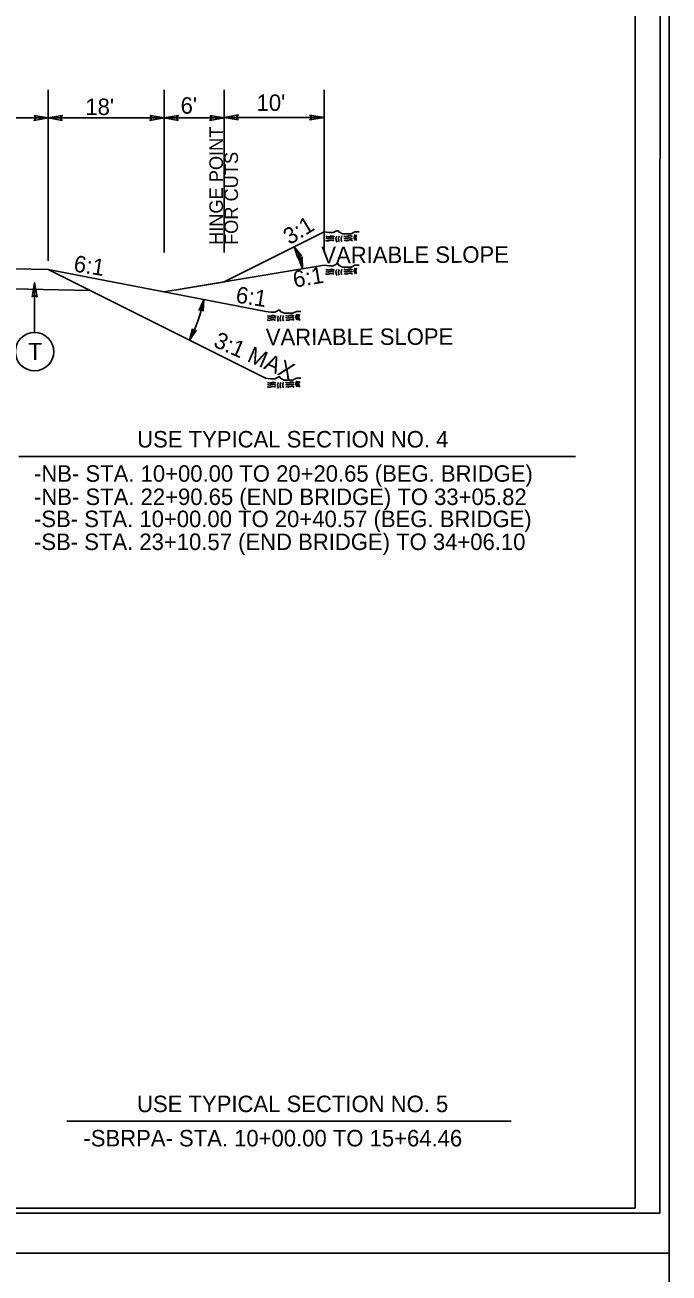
# Model space of a CAD drawing. Extents: x 2241081 to 2251104, y 658534 to 663427.
# Drawn here: x 2246759 to 2247081, y 660714 to 661339 of the extents above; entities that cross this region are included whole.
import ezdxf

# ---------------------------------------------------------------- set-up
doc = ezdxf.new("R2010")
doc.units = 0
for name, color, linetype in [('Old_Level_1', 7, 'Continuous'), ('Old_Level_2', 7, 'Continuous'), ('Prop Dimension', 7, 'Continuous'), ('Prop Dimension Text', 7, 'Continuous'), ('Prop PHM Text', 7, 'Continuous'), ('Sheet Cutting Line CELL', 7, 'Continuous'), ('Sheet Plan CELL', 7, 'Continuous'), ('Sheet Plot Border Inside CELL', 7, 'Continuous'), ('Sheet Plot Border Outside CELL', 7, 'Continuous'), ('Typical Hinge Slope Interstate CELL', 7, 'Continuous'), ('Typical ID Circle CELL', 7, 'Continuous'), ('Typical Terminator CELL', 7, 'Continuous'), ('Typical Text ID Circle CELL', 7, 'Continuous'), ('Typical Text Label CELL', 7, 'Continuous')]:
    doc.layers.add(name, color=color, linetype=linetype)

msp = doc.modelspace()

# ---------------------------------------------------------------- linework, layer by layer
at = {"layer": 'Old_Level_1'}
for p, q in [((2246908.21, 661235.45), (2246858.21, 661210.45)), ((2246858.21, 661210.45), (2246908.21, 661218.78)), ((2246770.2, 661216.62), (2246879.03, 661195.67)), ((2246858.21, 661210.45), (2246836.21, 661206.78))]:
    msp.add_line(p, q, dxfattribs=at)
for points in [[(2246908.21, 661235.45), (2246910.68, 661235.14), (2246911.29, 661235.14), (2246912.22, 661235.14), (2246912.83, 661235.14), (2246913.45, 661235.45), (2246914.07, 661235.76), (2246914.68, 661236.07), (2246915.3, 661236.07), (2246915.61, 661235.45), (2246916.22, 661235.14), (2246916.84, 661234.83), (2246917.46, 661234.53), (2246918.07, 661234.53), (2246918.69, 661234.53), (2246919.3, 661234.53), (2246919.92, 661234.53), (2246920.54, 661234.53), (2246921.15, 661234.53), (2246921.77, 661234.53), (2246922.39, 661234.83), (2246923, 661235.14), (2246923.62, 661235.45), (2246924.54, 661235.45), (2246925.16, 661235.45), (2246925.78, 661235.45)], [(2246908.21, 661218.78), (2246910.68, 661218.48), (2246911.29, 661218.48), (2246912.22, 661218.48), (2246912.83, 661218.48), (2246913.45, 661218.78), (2246914.07, 661219.09), (2246914.68, 661219.4), (2246915.3, 661219.4), (2246915.61, 661218.78), (2246916.22, 661218.48), (2246916.84, 661218.17), (2246917.46, 661217.86), (2246918.07, 661217.86), (2246918.69, 661217.86), (2246919.3, 661217.86), (2246919.92, 661217.86), (2246920.54, 661217.86), (2246921.15, 661217.86), (2246921.77, 661217.86), (2246922.39, 661218.17), (2246923, 661218.48), (2246923.62, 661218.78), (2246924.54, 661218.78), (2246925.16, 661218.78), (2246925.78, 661218.78)], [(2246879.03, 661195.67), (2246881.5, 661195.36), (2246882.11, 661195.36), (2246883.04, 661195.36), (2246883.66, 661195.36), (2246884.27, 661195.67), (2246884.89, 661195.98), (2246885.5, 661196.29), (2246886.12, 661196.29), (2246886.43, 661195.67), (2246887.05, 661195.36), (2246887.66, 661195.05), (2246888.28, 661194.75), (2246888.89, 661194.75), (2246889.51, 661194.75), (2246890.13, 661194.75), (2246890.74, 661194.75), (2246891.36, 661194.75), (2246891.97, 661194.75), (2246892.59, 661194.75), (2246893.21, 661195.05), (2246893.82, 661195.36), (2246894.44, 661195.67), (2246895.36, 661195.67), (2246895.98, 661195.67), (2246896.6, 661195.67)], [(2246879.01, 661162.21), (2246881.48, 661161.9), (2246882.09, 661161.9), (2246883.02, 661161.9), (2246883.63, 661161.9), (2246884.25, 661162.21), (2246884.87, 661162.52), (2246885.48, 661162.83), (2246886.1, 661162.83), (2246886.41, 661162.21), (2246887.02, 661161.9), (2246887.64, 661161.59), (2246888.26, 661161.28), (2246888.87, 661161.28), (2246889.49, 661161.28), (2246890.11, 661161.28), (2246890.72, 661161.28), (2246891.34, 661161.28), (2246891.95, 661161.28), (2246892.57, 661161.28), (2246893.19, 661161.59), (2246893.8, 661161.9), (2246894.42, 661162.21), (2246895.34, 661162.21), (2246895.96, 661162.21), (2246896.58, 661162.21)]]:
    msp.add_lwpolyline(points, dxfattribs=at)
for points in [[(2246913.19, 661230.94), (2246911.69, 661231.37), (2246910.1, 661230.96), (2246908.95, 661231.22)], [(2246913.19, 661230.94), (2246911.69, 661231.37), (2246910.1, 661230.96), (2246908.95, 661231.22)], [(2246913.35, 661232.03), (2246911.84, 661232.46), (2246910.25, 661232.05), (2246909.11, 661232.31)], [(2246913.35, 661232.03), (2246911.84, 661232.46), (2246910.25, 661232.05), (2246909.11, 661232.31)], [(2246913.39, 661232.97), (2246911.88, 661233.4), (2246910.29, 661233), (2246909.14, 661233.25)], [(2246913.39, 661232.97), (2246911.88, 661233.4), (2246910.29, 661233), (2246909.14, 661233.25)], [(2246914.63, 661233.26), (2246914.21, 661232.02), (2246914.66, 661230.37)], [(2246914.63, 661233.26), (2246914.21, 661232.02), (2246914.66, 661230.37)], [(2246915.84, 661233.37), (2246915.42, 661232.13), (2246915.87, 661230.48)], [(2246915.84, 661233.37), (2246915.42, 661232.13), (2246915.87, 661230.48)], [(2246917.15, 661233.47), (2246916.74, 661232.23), (2246917.18, 661230.58)], [(2246917.15, 661233.47), (2246916.74, 661232.23), (2246917.18, 661230.58)], [(2246922.41, 661233.12), (2246920.91, 661233.55), (2246919.32, 661233.14), (2246918.18, 661233.4)], [(2246922.41, 661233.12), (2246920.91, 661233.55), (2246919.32, 661233.14), (2246918.18, 661233.4)], [(2246922.42, 661232.07), (2246920.91, 661232.5), (2246919.33, 661232.09), (2246918.19, 661232.35)], [(2246922.42, 661232.07), (2246920.91, 661232.5), (2246919.33, 661232.09), (2246918.19, 661232.35)], [(2246922.54, 661231.01), (2246921.03, 661231.44), (2246919.44, 661231.04), (2246918.29, 661231.3)], [(2246922.54, 661231.01), (2246921.03, 661231.44), (2246919.44, 661231.04), (2246918.29, 661231.3)], [(2246923.74, 661234.09), (2246923.32, 661232.84), (2246923.77, 661231.2)], [(2246923.74, 661234.09), (2246923.32, 661232.84), (2246923.77, 661231.2)], [(2246924.52, 661234), (2246924.1, 661232.76), (2246924.56, 661231.11)], [(2246924.52, 661234), (2246924.1, 661232.76), (2246924.56, 661231.11)], [(2246923.74, 661217.42), (2246923.32, 661216.18), (2246923.77, 661214.53)], [(2246923.74, 661217.42), (2246923.32, 661216.18), (2246923.77, 661214.53)], [(2246924.52, 661217.34), (2246924.1, 661216.09), (2246924.56, 661214.45)], [(2246924.52, 661217.34), (2246924.1, 661216.09), (2246924.56, 661214.45)], [(2246913.19, 661214.27), (2246911.69, 661214.7), (2246910.1, 661214.3), (2246908.95, 661214.56)], [(2246913.19, 661214.27), (2246911.69, 661214.7), (2246910.1, 661214.3), (2246908.95, 661214.56)], [(2246913.35, 661215.37), (2246911.84, 661215.8), (2246910.25, 661215.39), (2246909.11, 661215.65)], [(2246913.35, 661215.37), (2246911.84, 661215.8), (2246910.25, 661215.39), (2246909.11, 661215.65)], [(2246913.39, 661216.31), (2246911.88, 661216.74), (2246910.29, 661216.33), (2246909.14, 661216.59)], [(2246913.39, 661216.31), (2246911.88, 661216.74), (2246910.29, 661216.33), (2246909.14, 661216.59)], [(2246914.63, 661216.6), (2246914.21, 661215.35), (2246914.66, 661213.71)], [(2246914.63, 661216.6), (2246914.21, 661215.35), (2246914.66, 661213.71)], [(2246915.84, 661216.71), (2246915.42, 661215.46), (2246915.87, 661213.81)], [(2246915.84, 661216.71), (2246915.42, 661215.46), (2246915.87, 661213.81)], [(2246917.15, 661216.81), (2246916.74, 661215.57), (2246917.18, 661213.92)], [(2246917.15, 661216.81), (2246916.74, 661215.57), (2246917.18, 661213.92)], [(2246922.41, 661216.45), (2246920.91, 661216.88), (2246919.32, 661216.48), (2246918.18, 661216.74)], [(2246922.41, 661216.45), (2246920.91, 661216.88), (2246919.32, 661216.48), (2246918.18, 661216.74)], [(2246922.42, 661215.41), (2246920.91, 661215.83), (2246919.33, 661215.43), (2246918.19, 661215.68)], [(2246922.42, 661215.41), (2246920.91, 661215.83), (2246919.33, 661215.43), (2246918.19, 661215.68)], [(2246922.54, 661214.35), (2246921.03, 661214.77), (2246919.44, 661214.38), (2246918.29, 661214.63)], [(2246922.54, 661214.35), (2246921.03, 661214.77), (2246919.44, 661214.38), (2246918.29, 661214.63)]]:
    msp.add_spline(points, degree=3, dxfattribs=at)
at = {"layer": 'Old_Level_2'}
for p, q in [((2246720.2, 661217.69), (2246770.2, 661216.62)), ((2246560.19, 661211.11), (2246791.1, 661206.17))]:
    msp.add_line(p, q, dxfattribs=at)
for points in [[(2246884.17, 661192.25), (2246882.66, 661192.68), (2246881.08, 661192.27), (2246879.93, 661192.53)], [(2246884.17, 661192.25), (2246882.66, 661192.68), (2246881.08, 661192.27), (2246879.93, 661192.53)], [(2246884.21, 661193.19), (2246882.7, 661193.62), (2246881.12, 661193.22), (2246879.97, 661193.47)], [(2246884.21, 661193.19), (2246882.7, 661193.62), (2246881.12, 661193.22), (2246879.97, 661193.47)], [(2246885.45, 661193.48), (2246885.03, 661192.24), (2246885.48, 661190.59)], [(2246885.45, 661193.48), (2246885.03, 661192.24), (2246885.48, 661190.59)], [(2246886.66, 661193.59), (2246886.24, 661192.34), (2246886.69, 661190.7)], [(2246886.66, 661193.59), (2246886.24, 661192.34), (2246886.69, 661190.7)], [(2246887.97, 661193.69), (2246887.56, 661192.45), (2246888, 661190.8)], [(2246887.97, 661193.69), (2246887.56, 661192.45), (2246888, 661190.8)], [(2246893.23, 661193.33), (2246891.73, 661193.77), (2246890.14, 661193.36), (2246889, 661193.62)], [(2246893.23, 661193.33), (2246891.73, 661193.77), (2246890.14, 661193.36), (2246889, 661193.62)], [(2246893.24, 661192.29), (2246891.74, 661192.72), (2246890.15, 661192.31), (2246889.01, 661192.57)], [(2246893.24, 661192.29), (2246891.74, 661192.72), (2246890.15, 661192.31), (2246889.01, 661192.57)], [(2246894.56, 661194.3), (2246894.14, 661193.06), (2246894.59, 661191.42)], [(2246894.56, 661194.3), (2246894.14, 661193.06), (2246894.59, 661191.42)], [(2246895.34, 661194.22), (2246894.92, 661192.98), (2246895.38, 661191.33)], [(2246895.34, 661194.22), (2246894.92, 661192.98), (2246895.38, 661191.33)], [(2246896.07, 661194.08), (2246895.65, 661192.84), (2246896.11, 661191.19)], [(2246896.07, 661194.08), (2246895.65, 661192.84), (2246896.11, 661191.19)], [(2246884.01, 661191.16), (2246882.51, 661191.59), (2246880.92, 661191.18), (2246879.77, 661191.44)], [(2246893.36, 661191.23), (2246891.86, 661191.66), (2246890.26, 661191.26), (2246889.11, 661191.51)], [(2246893.36, 661191.23), (2246891.86, 661191.66), (2246890.26, 661191.26), (2246889.11, 661191.51)], [(2246894.54, 661160.84), (2246894.12, 661159.6), (2246894.57, 661157.96)], [(2246894.54, 661160.84), (2246894.12, 661159.6), (2246894.57, 661157.96)], [(2246895.32, 661160.76), (2246894.9, 661159.52), (2246895.36, 661157.87)], [(2246895.32, 661160.76), (2246894.9, 661159.52), (2246895.36, 661157.87)], [(2246883.99, 661157.7), (2246882.49, 661158.13), (2246880.9, 661157.72), (2246879.75, 661157.98)], [(2246884.15, 661158.79), (2246882.64, 661159.22), (2246881.05, 661158.81), (2246879.91, 661159.07)], [(2246884.15, 661158.79), (2246882.64, 661159.22), (2246881.05, 661158.81), (2246879.91, 661159.07)], [(2246884.19, 661159.73), (2246882.68, 661160.16), (2246881.09, 661159.76), (2246879.95, 661160.01)], [(2246884.19, 661159.73), (2246882.68, 661160.16), (2246881.09, 661159.76), (2246879.95, 661160.01)], [(2246885.43, 661160.02), (2246885.01, 661158.78), (2246885.46, 661157.13)], [(2246885.43, 661160.02), (2246885.01, 661158.78), (2246885.46, 661157.13)], [(2246886.64, 661160.13), (2246886.22, 661158.88), (2246886.67, 661157.24)], [(2246886.64, 661160.13), (2246886.22, 661158.88), (2246886.67, 661157.24)], [(2246887.95, 661160.23), (2246887.54, 661158.99), (2246887.98, 661157.34)], [(2246887.95, 661160.23), (2246887.54, 661158.99), (2246887.98, 661157.34)], [(2246893.21, 661159.87), (2246891.71, 661160.31), (2246890.12, 661159.9), (2246888.98, 661160.16)], [(2246893.21, 661159.87), (2246891.71, 661160.31), (2246890.12, 661159.9), (2246888.98, 661160.16)], [(2246893.22, 661158.83), (2246891.71, 661159.25), (2246890.13, 661158.85), (2246888.99, 661159.11)], [(2246893.22, 661158.83), (2246891.71, 661159.25), (2246890.13, 661158.85), (2246888.99, 661159.11)], [(2246893.34, 661157.77), (2246891.83, 661158.2), (2246890.24, 661157.8), (2246889.09, 661158.05)], [(2246893.34, 661157.77), (2246891.83, 661158.2), (2246890.24, 661157.8), (2246889.09, 661158.05)], [(2246896.05, 661160.62), (2246895.63, 661159.38), (2246896.08, 661157.73)], [(2246896.05, 661160.62), (2246895.63, 661159.38), (2246896.08, 661157.73)]]:
    msp.add_spline(points, degree=3, dxfattribs=at)
at = {"layer": 'Prop Dimension'}
for centre, radius, start, end in [((2246878.27, 661216.12), 19.12, 2.56934, 38.33229), ((2246768.71, 661218.03), 81.05, 333.00981, 348.32106)]:
    msp.add_arc(centre, radius, start, end, dxfattribs=at)
at = {"layer": 'Prop Dimension Text'}
for p, q in [((2246770.2, 661220.98), (2246770.25, 661306.57)), ((2246828.21, 661225.1), (2246828.21, 661306.57)), ((2246858.21, 661225.1), (2246858.21, 661306.57)), ((2246908.21, 661225.1), (2246908.21, 661306.57)), ((2246710.24, 661292.54), (2246770.24, 661292.5)), ((2246770.2, 661292.5), (2246828.21, 661292.5)), ((2246828.21, 661292.5), (2246858.21, 661292.5)), ((2246858.21, 661292.89), (2246858.21, 661292.89)), ((2246858.21, 661292.76), (2246908.21, 661292.76)), ((2246908.21, 661292.89), (2246908.21, 661292.89))]:
    msp.add_line(p, q, dxfattribs=at)
at = {"layer": 'Sheet Cutting Line CELL'}
for p, q in [((2245397.32, 660724.27), (2247080.82, 660724.27)), ((2247080.82, 660724.27), (2245397.32, 660724.27))]:
    msp.add_line(p, q, dxfattribs=at)
at = {"layer": 'Sheet Plan CELL'}
for points in [[(2245563.81, 660746.78), (2245563.79, 661796.76), (2246863.78, 661796.79), (2246863.79, 661646.73), (2247063.83, 661646.72), (2247063.82, 660746.78)], [(2247063.85, 661796.78), (2245563.81, 661796.78), (2245563.81, 660746.78), (2247063.82, 660746.78)]]:
    msp.add_lwpolyline(points, close=True, dxfattribs=at)
at = {"layer": 'Sheet Plot Border Inside CELL'}
msp.add_lwpolyline([(2245410.32, 660744.27), (2247076.31, 660744.28), (2247076.33, 661799.27), (2245410.33, 661799.27)], close=True, dxfattribs=at)
at = {"layer": 'Sheet Plot Border Outside CELL'}
for points in [[(2245397.32, 660724.27), (2247080.82, 660724.27), (2247080.83, 661819.27), (2245397.33, 661819.27)], [(2245397.32, 659629.27), (2247080.82, 659629.27), (2247080.82, 660724.27), (2245397.32, 660724.27)]]:
    msp.add_lwpolyline(points, close=True, dxfattribs=at)
at = {"layer": 'Typical Hinge Slope Interstate CELL'}
for p, q in [((2246770.2, 661216.62), (2246879.01, 661162.21)), ((2246858.71, 661210.53), (2246828.21, 661205.45))]:
    msp.add_line(p, q, dxfattribs=at)
at = {"layer": 'Typical ID Circle CELL'}
msp.add_line((2246763.41, 661185.15), (2246763.41, 661210), dxfattribs=at)
msp.add_circle((2246763.41, 661175.53), 9.62, dxfattribs=at)
at = {"layer": 'Typical Terminator CELL'}
for points in [[(2246763.21, 661293.72), (2246770.24, 661292.5), (2246763.17, 661291.26), (2246764.07, 661292.51)], [(2246777.23, 661291.29), (2246770.2, 661292.5), (2246777.27, 661293.75), (2246776.37, 661292.5)], [(2246821.18, 661293.71), (2246828.21, 661292.5), (2246821.14, 661291.25), (2246822.04, 661292.5)], [(2246835.24, 661291.29), (2246828.21, 661292.5), (2246835.28, 661293.75), (2246834.38, 661292.5)], [(2246851.18, 661293.71), (2246858.21, 661292.5), (2246851.14, 661291.25), (2246852.04, 661292.5)], [(2246865.24, 661291.55), (2246858.21, 661292.76), (2246865.28, 661294.01), (2246864.38, 661292.76)], [(2246901.18, 661293.97), (2246908.21, 661292.76), (2246901.14, 661291.51), (2246902.04, 661292.76)], [(2246896.93, 661223.41), (2246893.27, 661227.98), (2246895.18, 661222.41), (2246895.72, 661223.55)], [(2246895.38, 661222.48), (2246897.37, 661216.98), (2246897.36, 661222.87), (2246896.48, 661221.96)], [(2246762.2, 661202.97), (2246763.41, 661210), (2246764.66, 661202.93), (2246763.41, 661203.83)], [(2246847.69, 661195.79), (2246848.09, 661201.62), (2246845.72, 661196.23), (2246846.89, 661196.7)], [(2246842.34, 661186.93), (2246840.93, 661181.25), (2246844.21, 661186.15), (2246842.97, 661185.88)]]:
    msp.add_lwpolyline(points, close=True, dxfattribs=at)
at = {"layer": 'Typical Text Label CELL'}
for p, q in [((2246755.58, 661123.01), (2247034.11, 661123.01)), ((2246779.56, 660790.28), (2247001.87, 660790.28))]:
    msp.add_line(p, q, dxfattribs=at)

# ---------------------------------------------------------------- texts
at = {"layer": 'Prop Dimension Text'}
for s, rotation, p in [("18'", 359.99993, (2246788.81, 661293.97)), ("6'", 359.99993, (2246836.47, 661294.63)), ("10'", 359.99993, (2246874.48, 661296.03)), ('6:1', 351.13422, (2246782.58, 661215.72)), ('6:1', 351.13422, (2246863.7, 661200.14))]:
    msp.add_text(s, height=8.25, rotation=rotation, dxfattribs=at).set_placement(p)
at = {"layer": 'Prop PHM Text'}
for s, height, p in [('HINGE POINT', 6.8193, (2246857.67, 661228.92)), ('FOR CUTS', 6.819, (2246865.18, 661228.92))]:
    msp.add_text(s, height=height, rotation=89.99993, dxfattribs=at).set_placement(p)
at = {"layer": 'Typical Hinge Slope Interstate CELL'}
for s, rotation, p in [('3:1', 31.55851, (2246891.04, 661228.73)), ('VARIABLE SLOPE', 0.18417, (2246906.9, 661219.76)), ('6:1', 9.46226, (2246893.41, 661207.55)), ('VARIABLE SLOPE', 0.18417, (2246879.1, 661178.69)), ('3:1 MAX', 336.3588, (2246852.39, 661178.24))]:
    msp.add_text(s, height=8.25, rotation=rotation, dxfattribs=at).set_placement(p)
at = {"layer": 'Typical Text ID Circle CELL'}
msp.add_text('T', height=8.61, rotation=359.99993, dxfattribs=at).set_placement((2246760.16, 661171.29))
at = {"layer": 'Typical Text Label CELL'}
for s, p in [('USE TYPICAL SECTION NO. 4', (2246814.74, 661127.55)), ('-NB- STA. 10+00.00 TO 20+20.65 (BEG. BRIDGE)', (2246763.13, 661110.39)), ('-NB- STA. 22+90.65 (END BRIDGE) TO 33+05.82', (2246763.13, 661098.74)), ('-SB- STA. 10+00.00 TO 20+40.57 (BEG. BRIDGE)', (2246763.13, 661087.68)), ('-SB- STA. 23+10.57 (END BRIDGE) TO 34+06.10', (2246763.13, 661076.21)), ('USE TYPICAL SECTION NO. 5', (2246814.68, 660794.82)), ('-SBRPA- STA. 10+00.00 TO 15+64.46', (2246787.85, 660777.65))]:
    msp.add_text(s, height=8.25, dxfattribs=at).set_placement(p)

doc.saveas('drawing.dxf')
